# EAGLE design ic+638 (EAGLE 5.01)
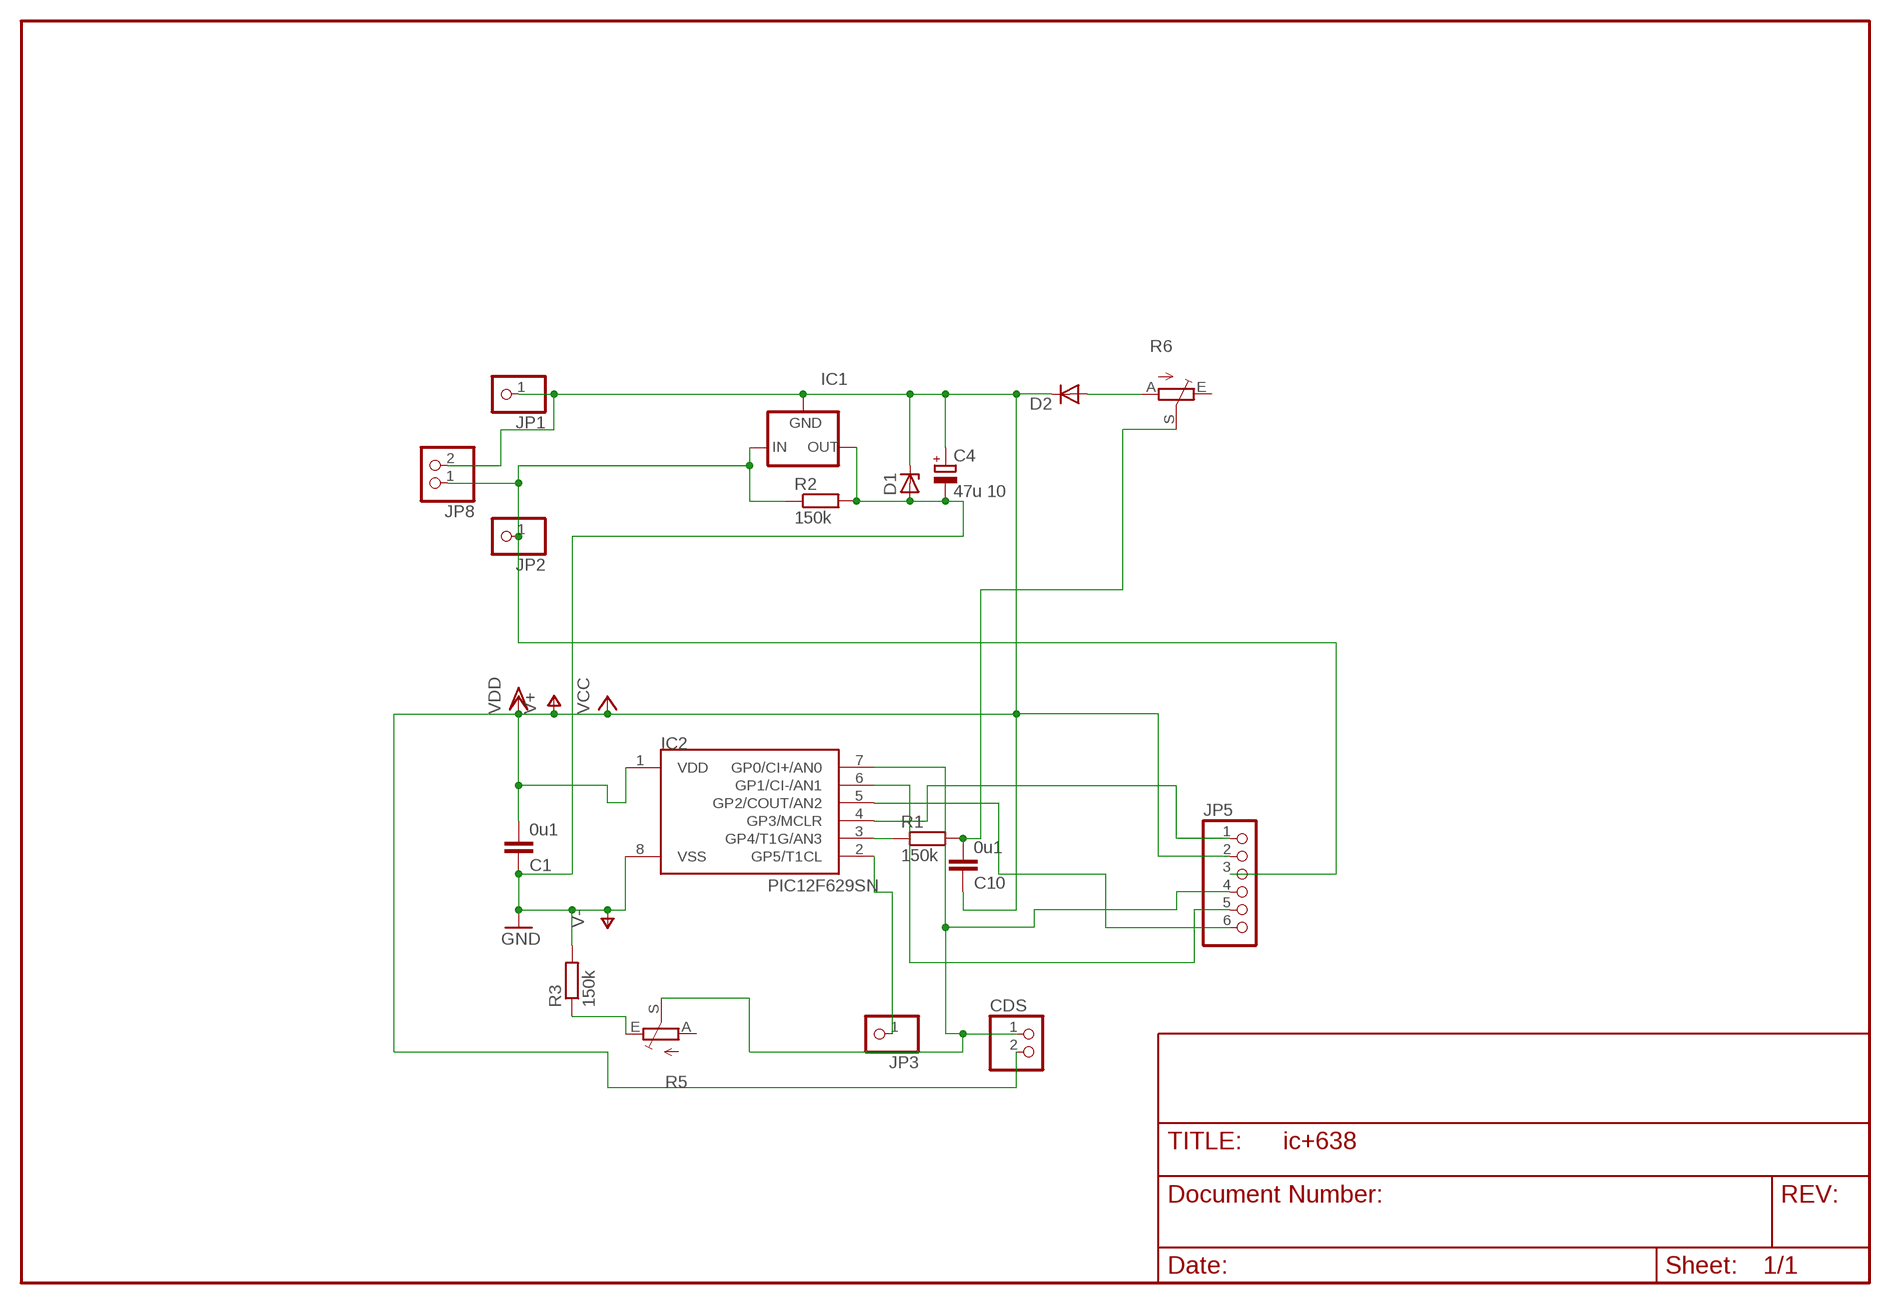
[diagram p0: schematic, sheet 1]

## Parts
C1  0u1  C-EUC1206  [C1206]
C4  47u 10  CPOL-EUE2.5-6  [E2,5-6]
C10  0u1  C-EUC1206  [C1206]
CDS  PINHD-1X2  [1X02]
D1  ZENER-DIODESOT23  [SOT23]
D2  DIODE-D-2.5  [D-2.5]
IC1  79LXX  [79LXX]
IC2  PIC12F629SN  [SO-08]
JP1  PINHD-1X1  [1X01]
JP2  PINHD-1X1  [1X01]
JP3  PINHD-1X1  [1X01]
JP5  PINHD-1X6  [1X06]
JP8  PINHD-1X2  [1X02]
R1  150k  R-EU_0204/2V  [0204V]
R2  150k  R-EU_0204/2V  [0204V]
R3  150k  R-EU_0204/2V  [0204V]
R5  TRIM_EU-CA6V  [CA6V]
R6  TRIM_EU-CA6V  [CA6V]

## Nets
CDS: IC2.2(GP5/T1CL) JP3.1
N$1: C10.2 R1.2 R6.S
N$2: IC2.5(GP2/COUT/AN2) JP5.6
N$3: IC2.4(GP3/MCLR) JP5.1
N$4: CDS.1 IC2.7(GP0/CI+/AN0) JP5.4 R5.S
N$5: R3.1 R5.E
N$7: D2.A R6.A
N$8: IC2.3(GP4/T1G/AN3) R1.1
N$10: IC1.IN JP2.1 JP5.3 JP8.1 R2.1
N$15: IC2.6(GP1/CI-/AN1) JP5.5
V+: C1.2 C4.+ C10.1 CDS.2 D1.3(C) D2.C IC1.GND IC2.1(VDD) JP1.1 JP5.2 JP8.2 ; supply symbol labelled VCC, VDD
V-: C1.1 C4.- D1.1(A) IC1.OUT IC2.8(VSS) R2.2 R3.2 ; supply symbol labelled GND
Unconnected: R5.A R6.E

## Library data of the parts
C1 C10 = rcl:C-EU: CAPACITOR, European symbol
C4 = rcl:CPOL-EU: POLARIZED CAPACITOR, European symbol
CDS JP8 = pinhead:PINHD-1X2: PIN HEADER
D1 = diode-1:ZENER-DIODE: Z-Diode
D2 = diode-1:DIODE-: DIODE
IC1 = v-reg:79LXX: VOLTAGE REGULATOR
IC2 = microchip-3:PIC12F6*: uPC nW 1k Program Flash memory 2x Timer Comparator 10b A/D converter/ 4xIN
JP1-JP3 = pinhead:PINHD-1X1: PIN HEADER
JP5 = pinhead(2):PINHD-1X6: PIN HEADER
R1-R3 = rcl:R-EU_: RESISTOR, European symbol
R5 R6 = pot:TRIM_EU-: POTENTIOMETER

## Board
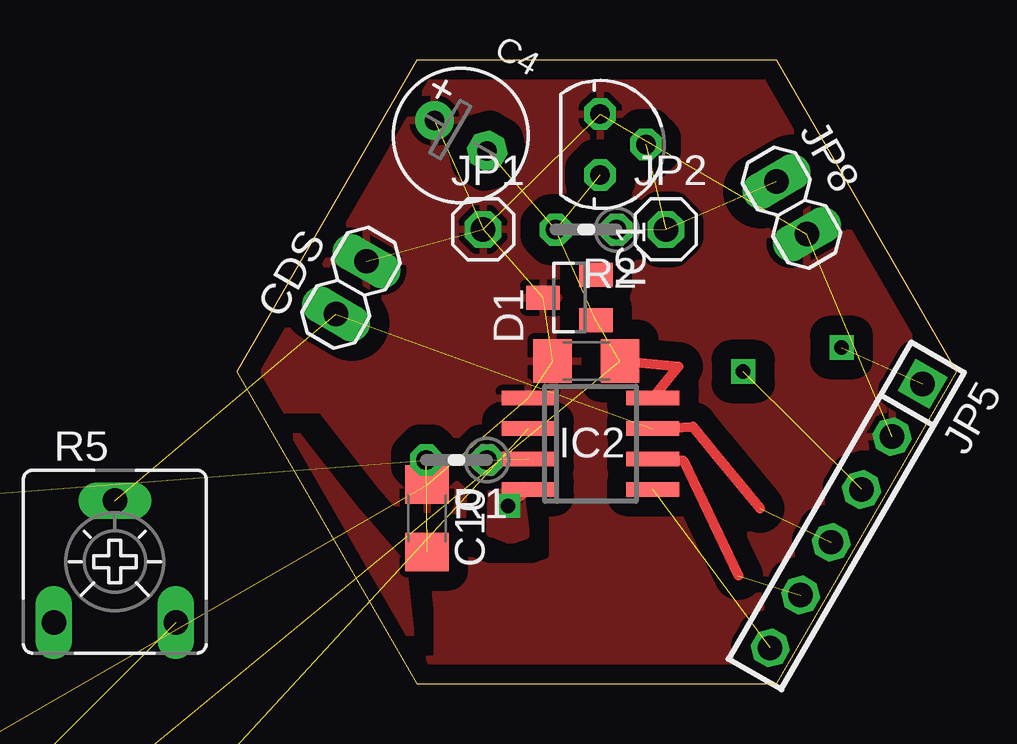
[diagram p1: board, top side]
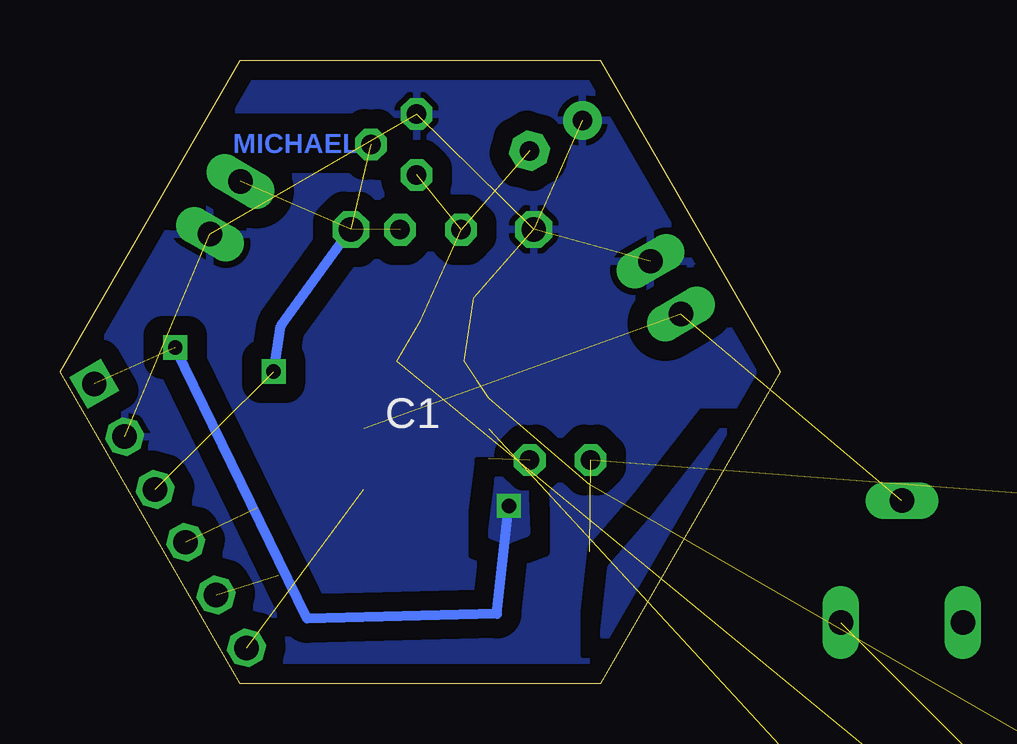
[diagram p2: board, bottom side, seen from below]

Size 30 x 25.98 mm. Coordinates in mm from the lower left corner, seen from the top.
Outline: 7.5,0 22.5,0 30,12.99 22.5,25.98 7.5,25.98 0,12.99 7.5,0
Copper layers (1*16): Top 0.035mm / dielectric 1.5mm / Bottom 0.035mm
Design rules "default *": minimum track width 10mil, minimum drill 24mil, track to track 8mil, track to pad 8mil, pad to pad 8mil, via to via 8mil, smd to smd 8mil, copper to edge 10mil, drill to drill 8mil, minimum pad ring 10mil, minimum via ring 8mil, stop-mask expansion 4mil, vias tented up to drill 0mil, thermal gap 10mil

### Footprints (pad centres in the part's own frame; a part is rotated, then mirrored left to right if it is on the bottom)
C1206 = smd 1.6 x 1.8: 1 -1.4,0; 2 1.4,0
E2,5-6 = drill 0.813 pad 1.6 round: + -1.27,0 | drill 0.813 pad 1.6 octagon: - 1.27,0
1X02 = drill 1.016 long: 1 -1.27,0; 2 1.27,0
SOT23 = smd 1 x 1.4: 1 -0.95,-1.1; 2 0.95,-1.1; 3 0,1.1
D-2.5 = drill 0.9 octagon: A 1.27,0; C -1.27,0
79LXX = drill 0.813 octagon: GND -1.27,0; IN 0,1.905; OUT 1.27,0
SO-08 = smd 0.6 x 2.2: 1 -1.905,-2.6; 2 -0.635,-2.6; 3 0.635,-2.6; 4 1.905,-2.6; 5 1.905,2.6; 6 0.635,2.6; 7 -0.635,2.6; 8 -1.905,2.6
1X01 = drill 1.016 octagon: 1 0,0
1X06 = drill 1.016 square: 1 -6.35,0 | drill 1.016 octagon: 2 -3.81,0; 3 -1.27,0; 4 1.27,0; 5 3.81,0; 6 6.35,0
0204V = drill 0.813 octagon: 1 -1.27,0; 2 1.27,0
CA6V = drill 1.016 long: A -2.54,-2.54; E 2.54,-2.54; S 0,2.54

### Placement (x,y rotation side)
C1  14.56,13.44 180 top
C4  9.34,22.83 330 top
C10  7.93,6.89 270 top
CDS  4.77,16.49 60 top
D1  13.86,16.08 90 top
D2  not placed on the board
IC1  15.14,22.46 270 top
IC2  14.74,9.99 270 top
JP1  10.26,18.92 0 top
JP2  17.88,18.92 0 top
JP3  not placed on the board
JP5  25.4,6.99 240 top
JP8  23.12,19.82 300 top
R1  9.16,9.31 180 top
R2  14.56,18.91 180 top
R3  not placed on the board
R5  -5.08,5.08 0 top
R6  not placed on the board

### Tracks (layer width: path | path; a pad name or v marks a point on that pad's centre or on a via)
CDS  (1 unrouted)
N$1  (2 unrouted)
  pour Top (isolate 0.61): 2.1,10.8 7.2,2.1 6.9,4.9 5,7.1
  pour Bottom (isolate 0.61): 2.2,10.7 7.3,2 7,4.8 5.1,7
N$2  (1 unrouted)
N$3  (via drill 0.6)  (1 unrouted)
  Top 0.406: v11.3,7.4 IC2.4
  Bottom 0.406: v25.2,14 19.7,2.7 11.8,2.9 v11.3,7.4
  pour Top (isolate 0.61): 10.7,8.8 11.7,8.5 12,6.2 11.4,6 10.6,6.3
  pour Bottom (isolate 0.61): 10.7,8.8 11.7,8.5 12,6.2 11.4,6 10.6,6.3
N$4  (3 unrouted)
  Top 0.406: IC2.7 19,10.7 19.9,9.6 21.8,7.3
N$5  (1 unrouted)
N$7  (1 unrouted)
N$8  (1 unrouted)
N$10  (via drill 0.6)  (4 unrouted)
  Bottom 0.406: v21.1,13 20.8,14.9 JP2.1
N$15  (1 unrouted)
  Top 0.406: IC2.6 18.6,9.3 20.9,4.5
V+  (10 unrouted)
  pour Bottom (isolate 0.813, rank 4): 22.69,0.45 6.94,0.85 -0.63,14.71 7.44,25.75 23.4,26.48 24.95,23.34 29.84,13.01
  pour Top (isolate 0.813, rank 4): 22.85,25.64 30.02,13.23 22.99,0.25 7.24,0.65 -0.28,14.57 8.01,25.74
V-  (5 unrouted)
  Top 0.406: C1.1 18.4,13.2 IC2.8

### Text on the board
Bottom: MICHAELS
